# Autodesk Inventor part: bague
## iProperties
Author: robert
Shininess: 25.0
PropertySet Name: _Private Model Information
Compacted: True
Length Units: 11269
Angle Units: 11283
Time Units: 11279
Mass Units: 11290
Length Display Precision: 3
Angle Display Precision: 2
Created: 2001-08
Part Number: bague
Material: Bronze (étain doux)
Document SubType Name: Modélisation
Designer: robert
Control State: 0
Master: False
Checked Out: False
PropertySet Name: Design Tracking Control
Density: 8.874
Volumn: 6.063273821428304
Area: 53.03008399259569
PropertySet Name: Model Information
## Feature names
1. Révolution1 [Revolution]
